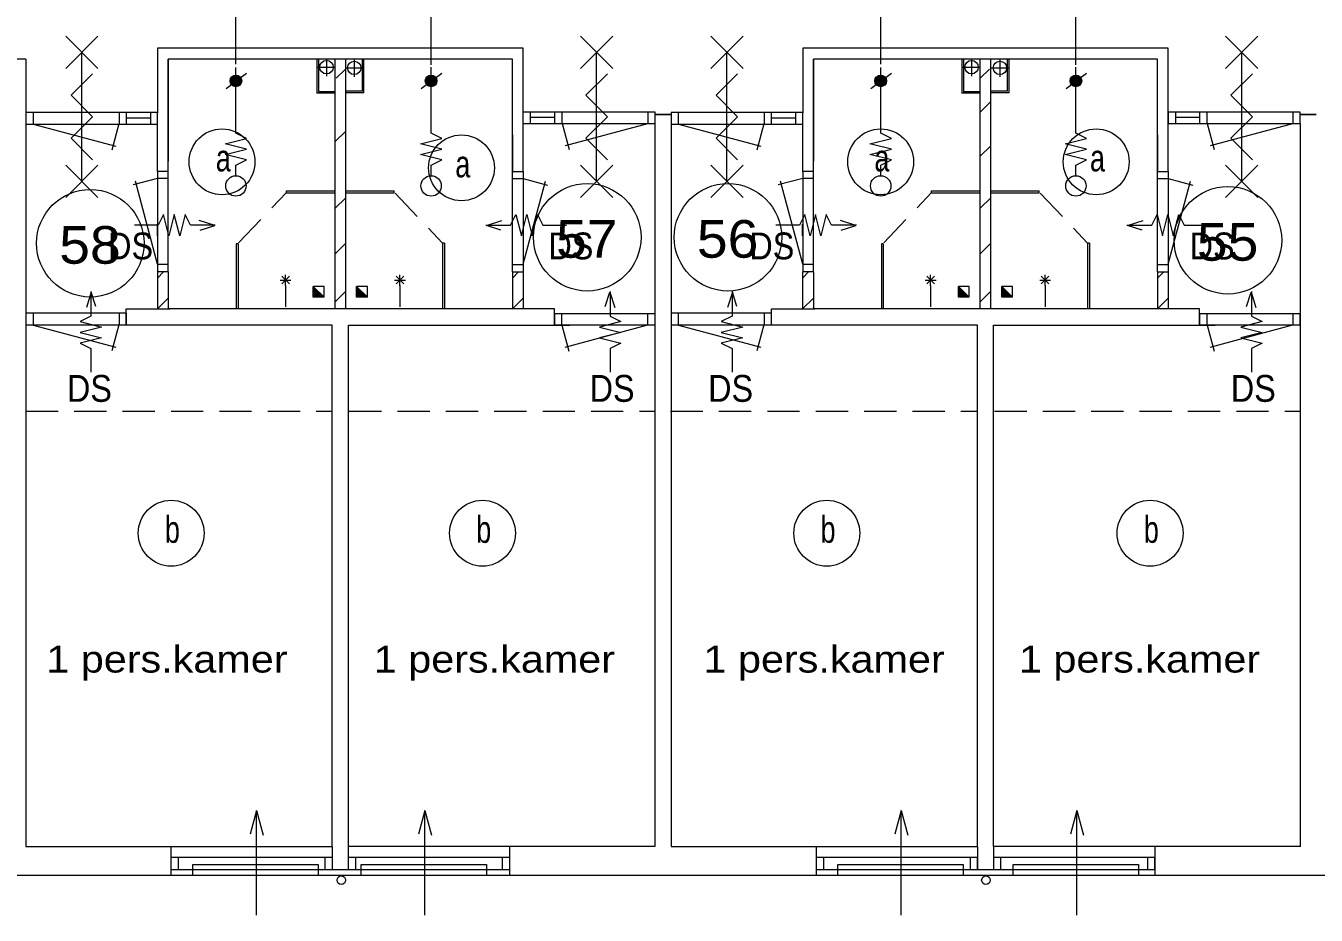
# Model space of a CAD drawing. Extents: x 295824 to 414724, y 24924 to 109024.
# Drawn here: x 308090 to 320090, y 30295 to 38568 of the extents above; entities that cross this region are included whole.
import ezdxf
from ezdxf.enums import TextEntityAlignment as Align

# ---------------------------------------------------------------- set-up
doc = ezdxf.new("R2010")
doc.units = 0
doc.header["$LTSCALE"] = 100
doc.linetypes.add('DOT_DASHED', pattern=[7.7, 5, -1.2, 0.3, -1.2])
doc.linetypes.add('MEDIUM_DASHED', pattern=[4.5, 3, -1.5])
for name, color, linetype, lineweight in [('1', 7, 'Continuous', 13), ('16', 7, 'Continuous', 13), ('24', 7, 'Continuous', 13), ('61', 7, 'Continuous', 13)]:
    doc.layers.add(name, color=color, linetype=linetype, lineweight=lineweight)

msp = doc.modelspace()

# ---------------------------------------------------------------- hatches: boundary and pattern name
at = {"layer": '24'}
for points in [[(310097.8, 38055.7, 1), (309989.2, 38055.7, 1)], [(311913.3, 38055.7, 1), (311804.7, 38055.7, 1)], [(316094.1, 38055.7, 1), (315985.5, 38055.7, 1)], [(317909.6, 38055.7, 1), (317801, 38055.7, 1)]]:
    msp.add_hatch(color=256, dxfattribs=at).paths.add_polyline_path(points)
at = {"layer": '61'}
for points in [[(310763.1, 36143.3), (310863.1, 36043.3), (310763.1, 36043.3)], [(311166.2, 36143.3), (311266.2, 36043.3), (311166.2, 36043.3)], [(316762.3, 36143.3), (316862.3, 36043.3), (316762.3, 36043.3)], [(317165.4, 36143.3), (317265.4, 36043.3), (317165.4, 36043.3)]]:
    msp.add_hatch(color=256, dxfattribs=at).paths.add_polyline_path(points)

# ---------------------------------------------------------------- linework, layer by layer
at = {"layer": '1'}
for p, q in [((310043.5, 38210.2), (310043.5, 39093.2)), ((311859, 38205.2), (311859, 39093.2)), ((316039.8, 38210.2), (316039.8, 39093.2)), ((317855.3, 38205.2), (317855.3, 39093.2))]:
    msp.add_line(p, q, dxfattribs=at)
at = {"layer": '16'}
for p, q in [((309470.8, 36814.4), (309420.8, 36614.4)), ((312748.2, 36814.4), (312798.2, 36614.4)), ((315433.7, 36814.4), (315383.7, 36614.4)), ((318711.2, 36814.4), (318761.2, 36614.4)), ((308594.4, 35716.2), (308794.4, 35666.2)), ((313624.7, 35716.2), (313424.7, 35666.2)), ((314557.3, 35716.2), (314757.3, 35666.2)), ((319587.6, 35716.2), (319387.6, 35666.2))]:
    msp.add_line(p, q, dxfattribs=at)
at = {"layer": '24'}
for p, q in [((310043.5, 37620.3), (310043.5, 38181)), ((311859, 37620.3), (311859, 38182.6)), ((316039.8, 37620.3), (316039.8, 38181)), ((317855.3, 37620.3), (317855.3, 38182.6)), ((309951.9, 37984.9), (310143.5, 38126.5)), ((311767.4, 37984.9), (311959, 38126.5)), ((315948.2, 37984.9), (316139.7, 38126.5)), ((317763.7, 37984.9), (317955.2, 38126.5)), ((309846.2, 36711), (309702, 36756)), ((312372.8, 36711), (312517, 36756)), ((315809.1, 36711), (315665, 36756)), ((318335.8, 36711), (318480, 36756)), ((309710.4, 36668.6), (309846.2, 36711)), ((312508.6, 36668.6), (312372.8, 36711)), ((315673.3, 36668.6), (315809.1, 36711)), ((318471.6, 36668.6), (318335.8, 36711)), ((308697.7, 36091.6), (308652.7, 35947.4)), ((308740.2, 35955.8), (308697.7, 36091.6)), ((313478.9, 35955.8), (313521.3, 36091.6)), ((313521.3, 36091.6), (313566.3, 35947.4)), ((314660.7, 36091.6), (314615.7, 35947.4)), ((314703.1, 35955.8), (314660.7, 36091.6)), ((319441.8, 35955.8), (319484.2, 36091.6)), ((319484.2, 36091.6), (319529.2, 35947.4)), ((310235, 31270.1), (310175.4, 31047.7)), ((311800.7, 31270.1), (311741.1, 31047.7)), ((316231.3, 31270.1), (316171.7, 31047.7)), ((317863.6, 31270.1), (317804, 31047.7))]:
    msp.add_line(p, q, dxfattribs=at)
for points in [[(310043.5, 37170.3), (310043.5, 37270.3), (310143.5, 37320.3), (309943.5, 37370.3), (310143.5, 37420.3), (309943.5, 37470.3), (310143.5, 37520.3), (310043.5, 37570.3), (310043.5, 37620.3)], [(311859, 37170.3), (311859, 37270.3), (311959, 37320.3), (311759, 37370.3), (311959, 37420.3), (311759, 37470.3), (311959, 37520.3), (311859, 37570.3), (311859, 37620.3)], [(316039.8, 37170.3), (316039.8, 37270.3), (316139.8, 37320.3), (315939.8, 37370.3), (316139.8, 37420.3), (315939.8, 37470.3), (316139.8, 37520.3), (316039.8, 37570.3), (316039.8, 37620.3)], [(317855.3, 37170.3), (317855.3, 37270.3), (317955.3, 37320.3), (317755.3, 37370.3), (317955.3, 37420.3), (317755.3, 37470.3), (317955.3, 37520.3), (317855.3, 37570.3), (317855.3, 37620.3)], [(309420.8, 36614.4), (309370.8, 36814.4), (309320.8, 36714.4), (309102, 36714.4)], [(309852, 36714.4), (309620.8, 36714.4), (309570.8, 36814.4), (309520.8, 36614.4), (309470.8, 36814.4)], [(312367, 36714.4), (312598.2, 36714.4), (312648.2, 36814.4), (312698.2, 36614.4), (312748.2, 36814.4)], [(312798.2, 36614.4), (312848.2, 36814.4), (312898.2, 36714.4), (313117, 36714.4)], [(315383.7, 36614.4), (315333.7, 36814.4), (315283.7, 36714.4), (315065, 36714.4)], [(315815, 36714.4), (315583.7, 36714.4), (315533.7, 36814.4), (315483.7, 36614.4), (315433.7, 36814.4)], [(318330, 36714.4), (318561.2, 36714.4), (318611.2, 36814.4), (318661.2, 36614.4), (318711.2, 36814.4)], [(318761.2, 36614.4), (318811.2, 36814.4), (318861.2, 36714.4), (319079.9, 36714.4)], [(308694.4, 36097.4), (308694.4, 35866.2), (308594.4, 35816.2), (308794.4, 35766.2), (308594.4, 35716.2)], [(313524.7, 36097.4), (313524.7, 35866.2), (313624.7, 35816.2), (313424.7, 35766.2), (313624.7, 35716.2)], [(314657.3, 36097.4), (314657.3, 35866.2), (314557.3, 35816.2), (314757.3, 35766.2), (314557.3, 35716.2)], [(319487.6, 36097.4), (319487.6, 35866.2), (319587.6, 35816.2), (319387.6, 35766.2), (319587.6, 35716.2)], [(308794.4, 35666.2), (308594.4, 35616.2), (308694.4, 35566.2), (308694.4, 35347.5)], [(313424.7, 35666.2), (313624.7, 35616.2), (313524.7, 35566.2), (313524.7, 35347.5)], [(314757.3, 35666.2), (314557.3, 35616.2), (314657.3, 35566.2), (314657.3, 35347.5)], [(319387.6, 35666.2), (319587.6, 35616.2), (319487.6, 35566.2), (319487.6, 35347.5)], [(310235, 30295.2), (310235, 31270.1), (310296.7, 31040)], [(311800.7, 30295.2), (311800.7, 31270.1), (311862.4, 31040)], [(316231.3, 30295.2), (316231.3, 31270.1), (316293, 31040)], [(317863.6, 30295.2), (317863.6, 31270.1), (317925.3, 31040)]]:
    msp.add_lwpolyline(points, dxfattribs=at)
for points in [[(309643.7, 30766), (310809.7, 30766), (310809.7, 30666), (309643.7, 30666)], [(311209.4, 30766), (312375.4, 30766), (312375.4, 30666), (311209.4, 30666)], [(315640, 30766), (316805.9, 30766), (316805.9, 30666), (315640, 30666)], [(317272.3, 30766), (318438.2, 30766), (318438.2, 30666), (317272.3, 30666)]]:
    msp.add_lwpolyline(points, close=True, dxfattribs=at)
for centre, radius in [((310043.5, 38055.7), 54.3), ((311859, 38055.7), 54.3), ((316039.8, 38055.7), 54.3), ((317855.3, 38055.7), 54.3), ((310043.5, 37078.6), 95), ((311859, 37078.6), 95), ((316039.8, 37078.6), 95), ((317855.3, 37078.6), 95)]:
    msp.add_circle(centre, radius, dxfattribs=at)
at = {"layer": '61'}
for p, q in [((308760.6, 38472.2), (308460.6, 38172.2)), ((308460.6, 38472.2), (308760.6, 38172.2)), ((313548.3, 38472.2), (313248.3, 38172.2)), ((313248.3, 38472.2), (313548.3, 38172.2)), ((314759.8, 38472.2), (314459.8, 38172.2)), ((314459.8, 38472.2), (314759.8, 38172.2)), ((319547.5, 38472.2), (319247.5, 38172.2)), ((319247.5, 38472.2), (319547.5, 38172.2)), ((308610.6, 37122.2), (308610.6, 38322.2)), ((313398.3, 37122.2), (313398.3, 38322.2)), ((314609.8, 37122.2), (314609.8, 38322.2)), ((319397.5, 37122.2), (319397.5, 38322.2)), ((308090.1, 38258.6), (308090.1, 30933.6)), ((309415.2, 37214.4), (309415.2, 38259)), ((310796.9, 38259), (310796.9, 37942.5)), ((310811.2, 38259.3), (310811.2, 37957.6)), ((310965.2, 35934), (310965.2, 38259)), ((311061.5, 38165.1), (310976.2, 38079.8)), ((311065.2, 35934), (311065.2, 38259)), ((311219.4, 37958.9), (311219.4, 38257.9)), ((311234.4, 37943.9), (311234.4, 38257.6)), ((315414.4, 37214.4), (315414.4, 38259)), ((316795.9, 38259), (316795.9, 37942.5)), ((316810.2, 38259.3), (316810.2, 37957.6)), ((316964.4, 35934), (316964.4, 38259)), ((317050.8, 38165.1), (316965.5, 38079.8)), ((317064.4, 35934), (317064.4, 38259)), ((317218.4, 37958.9), (317218.4, 38257.9)), ((317233.4, 37943.9), (317233.4, 38257.6)), ((310965.4, 37942.5), (310796.9, 37942.5)), ((310811.2, 37957.6), (310964.5, 37957.6)), ((311219.4, 37958.9), (311065.4, 37958.9)), ((311234.4, 37943.9), (311066.6, 37943.9)), ((312715.2, 37216.6), (312715.2, 38003.7)), ((316964.4, 37942.5), (316795.9, 37942.5)), ((316810.2, 37957.6), (316963.6, 37957.6)), ((317218.4, 37958.9), (317064.4, 37958.9)), ((317233.4, 37943.9), (317065.6, 37943.9)), ((318714.4, 37216.6), (318714.4, 38003.7)), ((317063.9, 37864.2), (316965.5, 37765.7)), ((308156.7, 37763.1), (308156.7, 37653.1)), ((308956.7, 37763.1), (308956.7, 37653.1)), ((309023.7, 37763.1), (309023.7, 37653.1)), ((309024.5, 37712.3), (309249.2, 37712.3)), ((309249.2, 37763.1), (309249.2, 37653.1)), ((312781.6, 37767), (312781.6, 37657)), ((313006.3, 37716.2), (312781.6, 37716.2)), ((313007.1, 37767), (313007.1, 37657)), ((313074.1, 37767), (313074.1, 37657)), ((313874.1, 37767), (313874.1, 37657)), ((313939.9, 37746.4), (314089.9, 37746.4)), ((313940.1, 37742.2), (313940.1, 30933.6)), ((313940.1, 37742.2), (314090.1, 37742.2)), ((314090.1, 37742.2), (314090.1, 30933.6)), ((314155.9, 37763.1), (314155.9, 37653.1)), ((314955.9, 37763.1), (314955.9, 37653.1)), ((315022.9, 37763.1), (315022.9, 37653.1)), ((315023.7, 37712.3), (315248.4, 37712.3)), ((315248.4, 37763.1), (315248.4, 37653.1)), ((318780.8, 37767), (318780.8, 37657)), ((319005.4, 37716.2), (318780.8, 37716.2)), ((319006.2, 37767), (319006.2, 37657)), ((319073.2, 37767), (319073.2, 37657)), ((319873.2, 37767), (319873.2, 37657)), ((319939.7, 37746), (320089.7, 37746)), ((319939.7, 37742.2), (320089.7, 37742.2)), ((308159.3, 37652.9), (308926.6, 37447.3)), ((308953.9, 37655.1), (308888.9, 37412.4)), ((309315.2, 37214.4), (309315.2, 37659)), ((311064.8, 37589), (310966.3, 37490.5)), ((313076.9, 37659), (313142, 37416.2)), ((313871.5, 37656.8), (313104.2, 37451.2)), ((314158.5, 37652.9), (314925.8, 37447.3)), ((314953.1, 37655.1), (314888, 37412.4)), ((315314.4, 37214.4), (315314.4, 37659)), ((319076.1, 37659), (319141.1, 37416.2)), ((319870.7, 37656.8), (319103.4, 37451.2)), ((319940.1, 37658.6), (319940.1, 30932.2)), ((312615.2, 37553.7), (312615.2, 37216.6)), ((317063.9, 37452.7), (316965.5, 37354.2)), ((318614.4, 37553.7), (318614.4, 37216.6)), ((308760.6, 37272.2), (308460.6, 36972.2)), ((308460.6, 37272.2), (308760.6, 36972.2)), ((309315.2, 37215.2), (309315.2, 36280.4)), ((309415.2, 37214.4), (309315.2, 37214.4)), ((309415.2, 36280.4), (309415.2, 37214.4)), ((312615.4, 36280), (312615.4, 37214)), ((312615.4, 37214), (312715.4, 37214)), ((312715.4, 37214), (312715.4, 36280)), ((313548.3, 37272.2), (313248.3, 36972.2)), ((313248.3, 37272.2), (313548.3, 36972.2)), ((314759.8, 37272.2), (314459.8, 36972.2)), ((314459.8, 37272.2), (314759.8, 36972.2)), ((315314.4, 37215.2), (315314.4, 36280.4)), ((315414.4, 37214.4), (315314.4, 37214.4)), ((315414.4, 36280.4), (315414.4, 37214.4)), ((318614.6, 36280), (318614.6, 37214)), ((318614.6, 37214), (318714.6, 37214)), ((318714.6, 37214), (318714.6, 36280)), ((319547.5, 37272.2), (319247.5, 36972.2)), ((319247.5, 37272.2), (319547.5, 36972.2)), ((309315.5, 37148.4), (309088.2, 37087.5)), ((309315.5, 36351), (309108.6, 37123.2)), ((309415.1, 37147.4), (309315.8, 37147.4)), ((312615.5, 37147), (312714.8, 37147)), ((312715.1, 37148), (312942.4, 37087.1)), ((312715.1, 36350.6), (312922, 37122.8)), ((315314.7, 37148.4), (315087.4, 37087.5)), ((315314.7, 36351), (315107.8, 37123.2)), ((315414.3, 37147.4), (315315, 37147.4)), ((318614.7, 37147), (318714, 37147)), ((318714.3, 37148), (318941.6, 37087.1)), ((318714.3, 36350.6), (318921.2, 37122.8)), ((310514.2, 37033.2), (310964.3, 37033.2)), ((310514.2, 37015.2), (310514.2, 37033.2)), ((310514.2, 37015.2), (310964.3, 37015.2)), ((311064.8, 36969), (310966.3, 36870.5)), ((311065.6, 37033.2), (311515.9, 37033.2)), ((316513.4, 37033.2), (316963.5, 37033.2)), ((316513.4, 37015.2), (316513.4, 37033.2)), ((316513.4, 37015.2), (316963.5, 37015.2)), ((317063.9, 36969), (316965.5, 36870.5)), ((317064.8, 37033.2), (317515.1, 37033.2)), ((309315.1, 36613.5), (309315.1, 36723.9)), ((315314.3, 36613.5), (315314.3, 36723.9)), ((310046.7, 36541.2), (310046.7, 35936.4)), ((310064.7, 36541.2), (310046.7, 36541.2)), ((310064.7, 36541.2), (310064.7, 35936.4)), ((311064.8, 36546.5), (310966.3, 36448)), ((311964.5, 36547.3), (311964.5, 35938.9)), ((311982.5, 36547.3), (311964.5, 36547.3)), ((311982.5, 36547.3), (311982.5, 35938.9)), ((316045.9, 36541.2), (316045.9, 35936.4)), ((316063.9, 36541.2), (316045.9, 36541.2)), ((316063.9, 36541.2), (316063.9, 35936.4)), ((317063.9, 36546.5), (316965.5, 36448)), ((317963.7, 36547.3), (317963.7, 35938.9)), ((317981.7, 36547.3), (317963.7, 36547.3)), ((317981.7, 36547.3), (317981.7, 35938.9)), ((309370.9, 36278.7), (309314.2, 36222)), ((309414.8, 36280.4), (309314.7, 36280.4)), ((309315, 36280.4), (309315, 35934)), ((309415.4, 36347.4), (309315.2, 36347.4)), ((309414.8, 36280), (309414.8, 35933.6)), ((310505.1, 36152.8), (310505.1, 36252.8)), ((311569.6, 36152.8), (311569.6, 36252.8)), ((312615.2, 36347), (312715.4, 36347)), ((312615.4, 36280), (312715.4, 36280)), ((312672.8, 36278.7), (312616.1, 36222)), ((312616.4, 36280.4), (312616.4, 35934)), ((312715.2, 36280.4), (312715.2, 35934)), ((315370, 36278.7), (315313.4, 36222)), ((315414, 36280.4), (315313.9, 36280.4)), ((315314.2, 36280.4), (315314.2, 35934)), ((315414.6, 36347.4), (315314.4, 36347.4)), ((315414, 36280), (315414, 35933.6)), ((316504.3, 36152.8), (316504.3, 36252.8)), ((317568.8, 36152.8), (317568.8, 36252.8)), ((318614.4, 36347), (318714.6, 36347)), ((318614.6, 36280), (318714.6, 36280)), ((318671.9, 36278.7), (318615.3, 36222)), ((318615.6, 36280.4), (318615.6, 35934)), ((318714.3, 36280.4), (318714.3, 35934)), ((310455.1, 36202.8), (310555.1, 36202.8)), ((310469.8, 36167.4), (310540.5, 36238.1)), ((310469.8, 36238.1), (310540.5, 36167.4)), ((310505.1, 36152.8), (310505.1, 35952.8)), ((311519.6, 36202.8), (311619.6, 36202.8)), ((311534.2, 36167.4), (311605, 36238.1)), ((311534.2, 36238.1), (311605, 36167.4)), ((311569.6, 36152.8), (311569.6, 35952.8)), ((316454.3, 36202.8), (316554.3, 36202.8)), ((316468.9, 36167.4), (316539.7, 36238.1)), ((316468.9, 36238.1), (316539.7, 36167.4)), ((316504.3, 36152.8), (316504.3, 35952.8)), ((317518.8, 36202.8), (317618.8, 36202.8)), ((317533.4, 36167.4), (317604.1, 36238.1)), ((317533.4, 36238.1), (317604.1, 36167.4)), ((317568.8, 36152.8), (317568.8, 35952.8)), ((309414.6, 36034.7), (309314.2, 35934.3)), ((311064.8, 36098.9), (310966.3, 36000.4)), ((312715.1, 36034.7), (312614.7, 35934.3)), ((315413.8, 36034.7), (315313.4, 35934.3)), ((317063.9, 36098.9), (316965.5, 36000.4)), ((318714.3, 36034.7), (318613.9, 35934.3)), ((308090.8, 35894.5), (308090.8, 35784.1)), ((309021.6, 35894.5), (308090.8, 35894.5)), ((308156.7, 35894.8), (308156.7, 35784.8)), ((308956.7, 35894.8), (308956.7, 35784.8)), ((309023.7, 35894.8), (309023.7, 35784.8)), ((313005, 35934), (309414.8, 35934)), ((313005.9, 35892.8), (313005.8, 35782.8)), ((313008, 35892.5), (313938.8, 35892.5)), ((313072.8, 35892.8), (313072.9, 35782.8)), ((313872.8, 35892.8), (313872.8, 35782.8)), ((314090, 35894.5), (314090, 35784.1)), ((315020.8, 35894.5), (314090, 35894.5)), ((314155.9, 35894.8), (314155.9, 35784.8)), ((314955.9, 35894.8), (314955.9, 35784.8)), ((315022.9, 35894.8), (315022.9, 35784.8)), ((319004.1, 35934), (315414, 35934)), ((319005, 35892.8), (319005, 35782.8)), ((319007.2, 35892.5), (319937.9, 35892.5)), ((319072, 35892.8), (319072, 35782.8)), ((319872, 35892.8), (319872, 35782.8)), ((310940.2, 35784), (308090.9, 35784)), ((308159.3, 35784.7), (308926.6, 35579.1)), ((308953.9, 35786.8), (308888.9, 35544.1)), ((310940.2, 35784), (308997.8, 35784)), ((311090.2, 35784), (313150.2, 35784)), ((313075.7, 35784.8), (313140.7, 35542.1)), ((313870.3, 35782.7), (313103, 35577.1)), ((316939.4, 35784), (314090.1, 35784)), ((314158.5, 35784.7), (314925.8, 35579.1)), ((314953.1, 35786.8), (314888, 35544.1)), ((316939.4, 35784), (314997, 35784)), ((317089.4, 35784), (319149.4, 35784)), ((319074.9, 35784.8), (319139.9, 35542.1)), ((319869.4, 35782.7), (319102.2, 35577.1)), ((309438.8, 30932), (309438.8, 30662)), ((310938.8, 30932), (310938.8, 30717.3)), ((311087.8, 30932), (311087.8, 30717.3)), ((312587.8, 30932), (312587.8, 30662)), ((315439.4, 30932), (315439.4, 30662)), ((316939.4, 30932), (316939.4, 30717.3)), ((317088.4, 30932), (317088.4, 30717.3)), ((318588.4, 30932), (318588.4, 30662)), ((309439, 30830.3), (309439, 30717.3)), ((310938, 30831.3), (309439.9, 30831.3)), ((309506, 30830.8), (309506, 30717.9)), ((310871, 30831.3), (310871, 30717.9)), ((310938, 30831.3), (310938, 30717.3)), ((311088, 30830.3), (311088, 30717.3)), ((312587, 30831.3), (311088.9, 30831.3)), ((311155, 30830.8), (311155, 30717.3)), ((312520, 30831.3), (312520, 30717.9)), ((312587, 30831.3), (312587, 30717.3)), ((315439.5, 30830.3), (315439.5, 30717.3)), ((316938.6, 30831.3), (315440.5, 30831.3)), ((315506.5, 30830.8), (315506.5, 30717.9)), ((316871.6, 30831.3), (316871.6, 30717.9)), ((316938.6, 30831.3), (316938.6, 30717.3)), ((317088.5, 30830.3), (317088.5, 30717.3)), ((318587.6, 30831.3), (317089.5, 30831.3)), ((317155.5, 30830.8), (317155.5, 30717.3)), ((318520.6, 30831.3), (318520.6, 30717.9)), ((318587.6, 30831.3), (318587.6, 30717.3)), ((326190, 30663.6), (307806, 30663.6)), ((311155, 30717.3), (309439, 30717.3)), ((312587, 30717.3), (311088, 30717.3)), ((317155.5, 30717.3), (315439.5, 30717.3)), ((318587.6, 30717.3), (317088.5, 30717.3))]:
    msp.add_line(p, q, dxfattribs=at)
at = {"layer": '61', "linetype": 'DOT_DASHED'}
for p, q in [((310801.4, 38184.2), (310965.4, 38184.2)), ((310801.5, 38184.2), (310965.6, 38184.2)), ((310886.6, 38258.4), (310886.6, 38099.1)), ((311061.2, 38176.8), (311225.3, 38176.8)), ((311144, 38257.1), (311144, 38093)), ((316800.5, 38184.2), (316964.6, 38184.2)), ((316885.6, 38258.4), (316885.6, 38099.1)), ((317060.3, 38176.8), (317224.3, 38176.8)), ((317148.8, 38257.1), (317148.8, 38093))]:
    msp.add_line(p, q, dxfattribs=at)
at = {"layer": '61', "linetype": 'MEDIUM_DASHED'}
for p, q in [((310069, 36548.8), (310513, 37016.1)), ((311523.3, 37012.1), (311965.2, 36547.1)), ((316068.2, 36548.8), (316512.2, 37016.1)), ((317522.5, 37012.1), (317964.3, 36547.1)), ((308090.1, 34984.3), (310940.1, 34984.3)), ((311096.4, 34984.3), (313946.4, 34984.3)), ((314085.9, 34984.3), (316936, 34984.3)), ((317097.7, 34984.3), (319947.8, 34984.3))]:
    msp.add_line(p, q, dxfattribs=at)
at = {"layer": '61'}
for points in [[(312715.2, 37759), (312715.2, 38359), (309315.2, 38359), (309315.2, 37759)], [(318714.4, 37759), (318714.4, 38359), (315314.4, 38359), (315314.4, 37759)], [(308090.1, 38258.6), (307832.8, 38258.6), (307832.8, 37776.3)], [(310940.4, 38259), (309415.2, 38259), (309415.2, 37309)], [(312615.2, 37033.2), (312615.2, 38259), (310735.2, 38259)], [(316939.6, 38259), (315414.4, 38259), (315414.4, 37309)], [(318614.4, 37033.2), (318614.4, 38259), (316734.4, 38259)], [(308710.6, 37322.2), (308510.6, 37522.2), (308710.6, 37722.2), (308510.6, 37922.2), (308710.6, 38122.2)], [(313498.3, 37322.2), (313298.3, 37522.2), (313498.3, 37722.2), (313298.3, 37922.2), (313498.3, 38122.2)], [(314709.8, 37322.2), (314509.8, 37522.2), (314709.8, 37722.2), (314509.8, 37922.2), (314709.8, 38122.2)], [(319497.5, 37322.2), (319297.5, 37522.2), (319497.5, 37722.2), (319297.5, 37922.2), (319497.5, 38122.2)], [(311065.6, 37015.2), (311515.9, 37015.2), (311515.9, 37033.2)], [(317064.8, 37015.2), (317515.1, 37015.2), (317515.1, 37033.2)], [(310863.1, 36043.3), (310763.1, 36043.3), (310763.1, 36143.3)], [(311266.2, 36043.3), (311166.2, 36043.3), (311166.2, 36143.3)], [(316862.3, 36043.3), (316762.3, 36043.3), (316762.3, 36143.3)], [(317265.4, 36043.3), (317165.4, 36043.3), (317165.4, 36143.3)], [(309024.2, 35784.1), (309024.2, 35934), (309429.6, 35934)], [(311090.2, 35784), (313005, 35784), (313005, 35934)], [(313938.8, 35892.5), (313938.8, 35782.1), (313005.4, 35782.1)], [(315023.4, 35784.1), (315023.4, 35934), (315428.8, 35934)], [(317089.4, 35784), (319004.1, 35784), (319004.1, 35934)], [(319937.9, 35892.5), (319937.9, 35782.1), (319004.6, 35782.1)], [(308090.1, 30933.6), (310940.1, 30933.6), (310940.1, 35783.6)], [(313940.1, 30933.6), (311090.1, 30933.6), (311090.1, 35783.6)], [(314090.1, 30933.6), (316940.1, 30933.6), (316940.1, 35783.6)], [(319940.1, 30933.6), (317090.1, 30933.6), (317090.1, 35783.6)]]:
    msp.add_lwpolyline(points, dxfattribs=at)
for points in [[(308090.8, 37762.8), (308090.8, 37652.4), (309315.1, 37652.4), (309315.1, 37762.8)], [(313940, 37766.6), (313940, 37656.3), (312715.7, 37656.3), (312715.7, 37766.6)], [(314090.2, 37762.8), (314090.2, 37652.4), (315314.5, 37652.4), (315314.5, 37762.8)], [(319939.2, 37766.6), (319939.2, 37656.3), (318714.9, 37656.3), (318714.9, 37766.6)], [(310863.1, 36043.3), (310863.1, 36143.3), (310763.1, 36143.3)], [(310763.1, 36143.3), (310863.1, 36043.3), (310763.1, 36043.3)], [(311266.2, 36043.3), (311266.2, 36143.3), (311166.2, 36143.3)], [(311166.2, 36143.3), (311266.2, 36043.3), (311166.2, 36043.3)], [(316862.3, 36043.3), (316862.3, 36143.3), (316762.3, 36143.3)], [(316762.3, 36143.3), (316862.3, 36043.3), (316762.3, 36043.3)], [(317265.4, 36043.3), (317265.4, 36143.3), (317165.4, 36143.3)], [(317165.4, 36143.3), (317265.4, 36043.3), (317165.4, 36043.3)]]:
    msp.add_lwpolyline(points, close=True, dxfattribs=at)
for centre, radius in [((310885.9, 38183.5), 62.5), ((311144, 38176.7), 62.5), ((316885, 38183.5), 62.5), ((317148.8, 38176.7), 62.5), ((309914.6, 37302.8), 306.3), ((316039.6, 37302.8), 306.3), ((318044.2, 37302.8), 306.3), ((312141.9, 37247.1), 306.3), ((313311, 36600.8), 500), ((314619.5, 36600.8), 500), ((308689.4, 36545.1), 500), ((319269, 36573), 500), ((309441.3, 33848), 306.3), ((312336.8, 33848), 306.3), ((315538.5, 33848), 306.3), ((318545.3, 33848), 306.3), ((311024, 30620.7), 40), ((317018.9, 30620.7), 40)]:
    msp.add_circle(centre, radius, dxfattribs=at)

# ---------------------------------------------------------------- texts
at = {"layer": '24', "width": 0.9}
for p in [(308855.6, 36395.4), (312950, 36395.4), (314818.6, 36395.4), (318913, 36395.4), (308472.5, 35070.4), (313333.1, 35070.4), (314435.5, 35070.4), (319296.1, 35070.4)]:
    msp.add_text('DS', height=250, dxfattribs=at).set_placement(p)
at = {"layer": '61'}
for s, width, p in [('a', 0.75, (309856.6, 37213.7)), ('a', 0.75, (312083.9, 37158)), ('a', 0.75, (315981.6, 37213.7)), ('a', 0.75, (317986.2, 37213.7)), ('b', 0.75, (309383.3, 33758.9)), ('b', 0.75, (312278.8, 33758.9)), ('b', 0.75, (315480.5, 33758.9)), ('b', 0.75, (318487.3, 33758.9)), ('1 pers.kamer', 1.15, (308280.3, 32552.1)), ('1 pers.kamer', 1.15, (311325.5, 32552.1)), ('1 pers.kamer', 1.15, (314392.1, 32552.1)), ('1 pers.kamer', 1.15, (317325.4, 32552.1))]:
    msp.add_text(s, height=250, dxfattribs=dict(at, width=width)).set_placement(p)
at = {"layer": '61', "width": 1.1}
for s, p in [('57', (313306.7, 36410.9)), ('56', (314616.6, 36410.9)), ('55', (319266.1, 36383.1)), ('58', (308686.5, 36355.2))]:
    msp.add_text(s, height=350, dxfattribs=at).set_placement(p, align=Align.CENTER)

doc.saveas('drawing.dxf')
